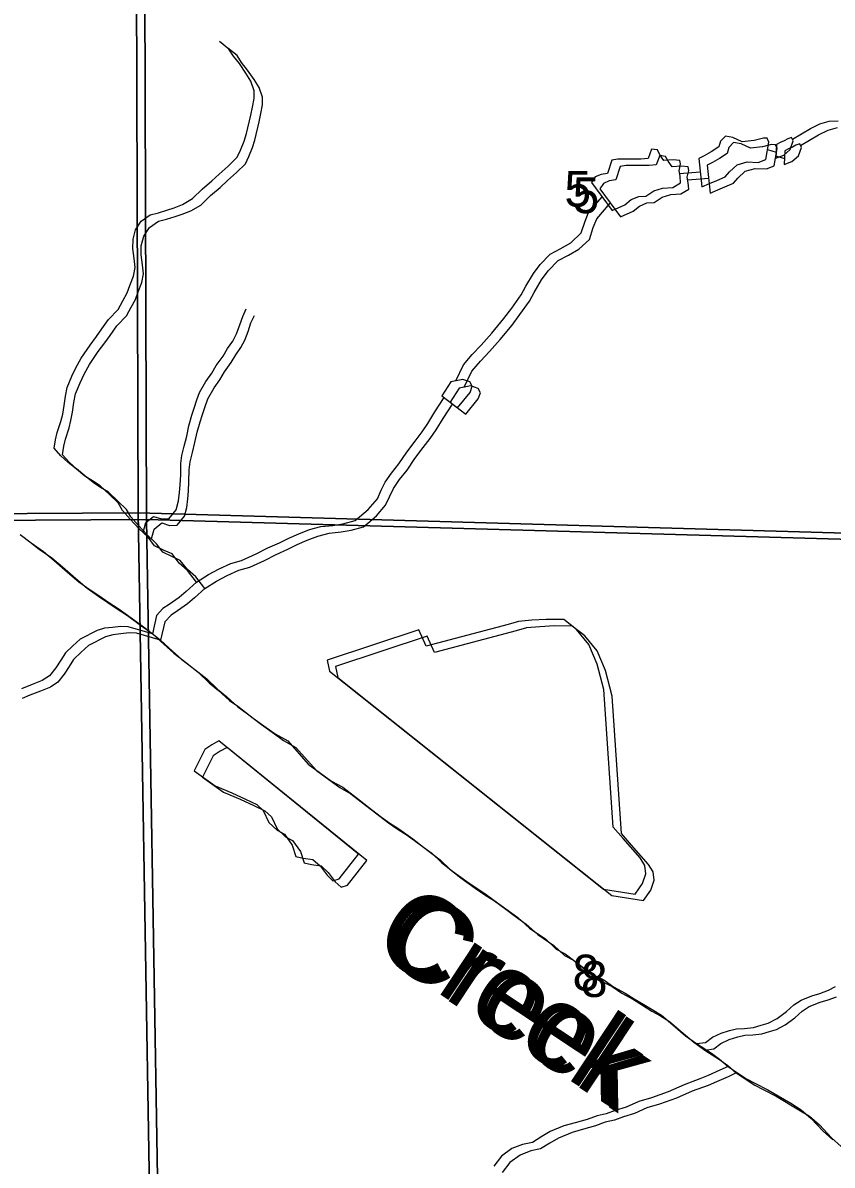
# Model space of a CAD drawing. Extents: x -21.1 to 50.3, y 0 to 22.1.
# Drawn here: x 44.997 to 45.942, y 17.965 to 19.298 of the extents above; entities that cross this region are included whole.
import ezdxf

# ---------------------------------------------------------------- set-up
doc = ezdxf.new("R2010")
doc.units = 0
for name, color, linetype in [('GM_X_Major_River', 7, 'Continuous'), ('GM_X_Major_River_Text', 7, 'Continuous'), ('GM_X_Minor_Lake', 7, 'Continuous'), ('GM_X_Minor_River', 7, 'Continuous'), ('GM_X_Section', 7, 'Continuous'), ('GM_X_Section_Text', 7, 'Continuous')]:
    doc.layers.add(name, color=color, linetype=linetype)

msp = doc.modelspace()

# ---------------------------------------------------------------- linework, layer by layer
at = {"layer": 'GM_X_Major_River'}
for points in [[(44.9936, 18.7011), (45.005, 18.6925), (45.0161, 18.6839), (45.0306, 18.6737), (45.0432, 18.6632), (45.0589, 18.6497), (45.0719, 18.6384), (45.0852, 18.629), (45.0963, 18.6215), (45.1058, 18.6151), (45.1192, 18.6065), (45.1329, 18.5964), (45.1474, 18.5859), (45.1577, 18.5776), (45.1673, 18.5689), (45.1826, 18.555), (45.1979, 18.5434), (45.2116, 18.5325), (45.2242, 18.5204), (45.2349, 18.5114), (45.2479, 18.4998), (45.2575, 18.493), (45.2754, 18.4791), (45.2907, 18.4682), (45.3014, 18.4607), (45.3158, 18.4525), (45.3396, 18.4254), (45.3541, 18.4149), (45.3671, 18.4055), (45.38, 18.3984), (45.3972, 18.3852), (45.4102, 18.3751), (45.4239, 18.3646), (45.4339, 18.3574), (45.4457, 18.3499), (45.4617, 18.3383), (45.4743, 18.3285), (45.4842, 18.3214), (45.4953, 18.3105), (45.5083, 18.3004), (45.5251, 18.2883), (45.5377, 18.2797), (45.5476, 18.2733), (45.561, 18.2636), (45.5705, 18.2564), (45.5846, 18.2463), (45.5984, 18.2339), (45.6171, 18.2212), (45.6293, 18.2095), (45.64, 18.2039), (45.6511, 18.1956), (45.6621, 18.1866), (45.6751, 18.1784), (45.685, 18.1735), (45.6965, 18.1656), (45.7098, 18.1581), (45.7205, 18.1514), (45.7315, 18.1447), (45.7414, 18.139), (45.7521, 18.1323), (45.7655, 18.121), (45.7804, 18.1082), (45.7934, 18.0992), (45.8105, 18.088), (45.8201, 18.0812), (45.83, 18.0726), (45.8414, 18.0647), (45.8518, 18.058), (45.8613, 18.0531), (45.8765, 18.0453), (45.9032, 18.0295), (45.9154, 18.022), (45.9272, 18.0119), (45.941, 17.9968), (45.9525, 17.9867)], [(44.9954, 18.7), (45.0065, 18.6914), (45.021, 18.6812), (45.0336, 18.6707), (45.0492, 18.6572), (45.0622, 18.6459), (45.0756, 18.6365), (45.0867, 18.629), (45.0962, 18.6226), (45.1095, 18.614), (45.1233, 18.6039), (45.1378, 18.5934), (45.1481, 18.5851), (45.1577, 18.5764), (45.173, 18.5625), (45.1882, 18.5509), (45.202, 18.54), (45.2146, 18.5279), (45.2253, 18.5189), (45.2383, 18.5073), (45.2478, 18.5005), (45.2658, 18.4866), (45.281, 18.4757), (45.2917, 18.4682), (45.3062, 18.46), (45.3299, 18.4329), (45.3444, 18.4224), (45.3574, 18.413), (45.3704, 18.4059), (45.3876, 18.3927), (45.4005, 18.3826), (45.4143, 18.3721), (45.4242, 18.3649), (45.436, 18.3574), (45.4521, 18.3458), (45.4647, 18.336), (45.4746, 18.3289), (45.4857, 18.318), (45.4987, 18.3079), (45.5155, 18.2958), (45.528, 18.2872), (45.538, 18.2808), (45.5513, 18.2711), (45.5609, 18.264), (45.575, 18.2538), (45.5887, 18.2414), (45.6074, 18.2287), (45.6197, 18.217), (45.6303, 18.2114), (45.6414, 18.2031), (45.6525, 18.1941), (45.6655, 18.1859), (45.6754, 18.181), (45.6868, 18.1731), (45.7002, 18.1656), (45.7108, 18.1589), (45.7219, 18.1522), (45.7318, 18.1465), (45.7425, 18.1398), (45.7559, 18.1285), (45.7708, 18.1157), (45.7837, 18.1067), (45.8009, 18.0955), (45.8104, 18.0887), (45.8204, 18.0801), (45.8318, 18.0722), (45.8421, 18.0655), (45.8516, 18.0606), (45.8669, 18.0528), (45.8936, 18.037), (45.9058, 18.0295), (45.9176, 18.0194), (45.9314, 18.0043), (45.9429, 17.9942)]]:
    msp.add_lwpolyline(points, dxfattribs=at)
at = {"layer": 'GM_X_Minor_Lake'}
for points in [[(45.7898, 19.107), (45.7989, 19.1109), (45.8072, 19.1144), (45.817, 19.1186), (45.8222, 19.1244), (45.8309, 19.1328), (45.8426, 19.136), (45.8555, 19.1354), (45.8646, 19.1389), (45.8681, 19.159), (45.8662, 19.1636), (45.8616, 19.1639), (45.851, 19.1611), (45.837, 19.1595), (45.826, 19.1647), (45.8172, 19.1661), (45.8116, 19.1603), (45.8098, 19.1535), (45.8007, 19.1477), (45.7925, 19.143), (45.7864, 19.1399)], [(45.8763, 19.1405), (45.8854, 19.144), (45.8929, 19.1506), (45.8965, 19.1605), (45.8946, 19.1646), (45.8901, 19.1631), (45.8859, 19.1607), (45.8814, 19.1588), (45.8769, 19.1565)], [(45.6851, 19.0793), (45.6998, 19.0859), (45.7073, 19.092), (45.716, 19.0956), (45.7243, 19.096), (45.7338, 19.1022), (45.744, 19.1053), (45.7557, 19.1062), (45.7647, 19.1116), (45.7643, 19.1192), (45.7631, 19.1257), (45.7649, 19.1336), (45.7641, 19.1378), (45.7561, 19.1385), (45.7455, 19.1376), (45.7409, 19.1444), (45.7378, 19.15), (45.7309, 19.1511), (45.7269, 19.1401), (45.7185, 19.1392), (45.6916, 19.1393), (45.6848, 19.1381), (45.6797, 19.1225), (45.6721, 19.1213), (45.6653, 19.1185), (45.6608, 19.112)], [(45.7995, 19.0995), (45.8085, 19.1034), (45.8168, 19.1069), (45.8266, 19.1111), (45.8319, 19.1169), (45.8405, 19.1253), (45.8522, 19.1285), (45.8651, 19.1279), (45.8742, 19.1314), (45.8778, 19.1515), (45.8758, 19.1561), (45.8713, 19.1564), (45.8607, 19.1536), (45.8467, 19.152), (45.8356, 19.1572), (45.8269, 19.1586), (45.8212, 19.1528), (45.8194, 19.146), (45.8104, 19.1402), (45.8021, 19.1355), (45.7961, 19.1324)], [(45.8769, 19.1565), (45.8763, 19.1405)], [(45.8859, 19.133), (45.895, 19.1365), (45.9025, 19.1431), (45.9062, 19.153), (45.9042, 19.1571), (45.8997, 19.1556), (45.8956, 19.1532), (45.891, 19.1513), (45.8865, 19.149)], [(45.6947, 19.0718), (45.7094, 19.0784), (45.717, 19.0845), (45.7256, 19.0881), (45.734, 19.0885), (45.7434, 19.0947), (45.7536, 19.0978), (45.7653, 19.0987), (45.7744, 19.1041), (45.7739, 19.1117), (45.7727, 19.1182), (45.7745, 19.1261), (45.7737, 19.1303), (45.7657, 19.131), (45.7551, 19.1301), (45.7505, 19.1369), (45.7474, 19.1425), (45.7406, 19.1436), (45.7365, 19.1326), (45.7282, 19.1317), (45.7013, 19.1318), (45.6944, 19.1306), (45.6893, 19.115), (45.6817, 19.1138), (45.6749, 19.111), (45.6705, 19.1045)], [(45.7864, 19.1399), (45.7898, 19.107)], [(45.8865, 19.149), (45.8859, 19.133)], [(45.7961, 19.1324), (45.7995, 19.0995)], [(45.6608, 19.112), (45.6851, 19.0793)], [(45.6705, 19.1045), (45.6947, 19.0718)], [(45.5045, 18.8489), (45.5191, 18.8669), (45.5217, 18.8741), (45.5189, 18.8791), (45.5106, 18.882), (45.4966, 18.8792), (45.4861, 18.8631)], [(45.5141, 18.8414), (45.5287, 18.8594), (45.5313, 18.8666), (45.5286, 18.8716), (45.5202, 18.8745), (45.5062, 18.8717), (45.4958, 18.8556)], [(45.4861, 18.8631), (45.5045, 18.8489)], [(45.4958, 18.8556), (45.5141, 18.8414)], [(45.3523, 18.5544), (45.3551, 18.5415), (45.675, 18.2869), (45.7119, 18.2812), (45.7204, 18.2935), (45.7245, 18.3049), (45.7232, 18.3147), (45.7178, 18.3234), (45.6979, 18.346), (45.6863, 18.3595), (45.6754, 18.5199), (45.6675, 18.5498), (45.6578, 18.5728), (45.6435, 18.5901), (45.6286, 18.6017), (45.6081, 18.6019), (45.5911, 18.6009), (45.5756, 18.5996), (45.5635, 18.5961), (45.4678, 18.5708), (45.4592, 18.5897)], [(45.3619, 18.5469), (45.3647, 18.534), (45.6846, 18.2794), (45.7215, 18.2737), (45.7301, 18.2859), (45.7341, 18.2974), (45.7329, 18.3072), (45.7275, 18.3159), (45.7075, 18.3385), (45.696, 18.352), (45.6851, 18.5124), (45.6771, 18.5423), (45.6674, 18.5653), (45.6532, 18.5826), (45.6383, 18.5942), (45.6178, 18.5944), (45.6007, 18.5934), (45.5852, 18.5921), (45.5731, 18.5886), (45.4774, 18.5633), (45.4689, 18.5822)], [(45.4592, 18.5897), (45.3523, 18.5544)], [(45.4689, 18.5822), (45.3619, 18.5469)], [(45.2259, 18.46), (45.2177, 18.4554), (45.2094, 18.45), (45.1971, 18.4252), (45.2216, 18.4076), (45.241, 18.3995), (45.257, 18.3921), (45.27, 18.3858), (45.2777, 18.379), (45.2843, 18.365), (45.2939, 18.3557), (45.3023, 18.3512), (45.3115, 18.3384), (45.3158, 18.3252), (45.3242, 18.3233), (45.3356, 18.3216), (45.344, 18.3141), (45.3521, 18.3032), (45.359, 18.2968), (45.3662, 18.2991), (45.389, 18.3278)], [(45.389, 18.3278), (45.2259, 18.46)], [(45.2356, 18.4525), (45.2273, 18.4479), (45.219, 18.4425), (45.2068, 18.4177), (45.2312, 18.4001), (45.2507, 18.392), (45.2667, 18.3846), (45.2796, 18.3783), (45.2873, 18.3715), (45.2939, 18.3575), (45.3035, 18.3482), (45.3119, 18.3437), (45.3211, 18.3309), (45.3255, 18.3177), (45.3338, 18.3158), (45.3452, 18.3141), (45.3536, 18.3066), (45.3617, 18.2957), (45.3686, 18.2893), (45.3758, 18.2916), (45.3986, 18.3203)], [(45.3986, 18.3203), (45.2356, 18.4525)]]:
    msp.add_lwpolyline(points, dxfattribs=at)
at = {"layer": 'GM_X_Minor_River'}
for points in [[(45.1997, 18.6454), (45.1891, 18.659), (45.1795, 18.6677), (45.1711, 18.6783), (45.1619, 18.6824), (45.1508, 18.688), (45.1432, 18.6979), (45.1325, 18.708), (45.1221, 18.719), (45.1133, 18.7292), (45.1083, 18.7379), (45.098, 18.7477), (45.0873, 18.7579), (45.0781, 18.7636), (45.0693, 18.7692), (45.0597, 18.7772), (45.0498, 18.7851), (45.0414, 18.793), (45.0333, 18.8017), (45.0352, 18.8116), (45.037, 18.82), (45.0412, 18.8329), (45.0434, 18.8416), (45.0452, 18.8515), (45.0467, 18.8626), (45.0485, 18.8728), (45.0542, 18.8858), (45.0587, 18.8957), (45.0651, 18.9071), (45.0753, 18.922), (45.0829, 18.9323), (45.0893, 18.941), (45.0968, 18.9521), (45.1082, 18.9639), (45.1138, 18.9739), (45.1187, 18.983), (45.1217, 18.9917), (45.1262, 19.0028), (45.1281, 19.0127), (45.1269, 19.0233), (45.1253, 19.0351), (45.1256, 19.0457), (45.1286, 19.0567), (45.135, 19.067), (45.1456, 19.0743), (45.1551, 19.0766), (45.165, 19.0797), (45.1734, 19.0824), (45.1832, 19.0863), (45.195, 19.0932), (45.2064, 19.1043), (45.2177, 19.1138), (45.2261, 19.1219), (45.2367, 19.131), (45.2473, 19.1414), (45.251, 19.1497), (45.2555, 19.1604), (45.2581, 19.1691), (45.2633, 19.1905), (45.2652, 19.2), (45.267, 19.2102), (45.267, 19.219), (45.2631, 19.2303), (45.2574, 19.2398), (45.2497, 19.2508), (45.2428, 19.2595), (45.2374, 19.2678), (45.2267, 19.2765)], [(45.2093, 18.6379), (45.1987, 18.6515), (45.1891, 18.6602), (45.1807, 18.6708), (45.1716, 18.6749), (45.1605, 18.6805), (45.1528, 18.6903), (45.1421, 18.7005), (45.1318, 18.7115), (45.1229, 18.7217), (45.1179, 18.7304), (45.1076, 18.7402), (45.0969, 18.7504), (45.0877, 18.7561), (45.0789, 18.7617), (45.0694, 18.7697), (45.0594, 18.7776), (45.051, 18.7855), (45.043, 18.7942), (45.0448, 18.8041), (45.0467, 18.8125), (45.0508, 18.8254), (45.053, 18.8341), (45.0549, 18.844), (45.0563, 18.8551), (45.0582, 18.8653), (45.0638, 18.8783), (45.0683, 18.8882), (45.0747, 18.8996), (45.0849, 18.9145), (45.0925, 18.9248), (45.0989, 18.9335), (45.1065, 18.9446), (45.1178, 18.9564), (45.1235, 18.9664), (45.1284, 18.9755), (45.1314, 18.9842), (45.1359, 18.9953), (45.1377, 19.0052), (45.1365, 19.0158), (45.1349, 19.0276), (45.1352, 19.0382), (45.1382, 19.0492), (45.1446, 19.0595), (45.1553, 19.0668), (45.1648, 19.0691), (45.1746, 19.0722), (45.183, 19.0749), (45.1929, 19.0788), (45.2046, 19.0857), (45.216, 19.0968), (45.2274, 19.1063), (45.2357, 19.1144), (45.2463, 19.1235), (45.2569, 19.1339), (45.2607, 19.1422), (45.2652, 19.1529), (45.2678, 19.1616), (45.273, 19.1829), (45.2748, 19.1925), (45.2767, 19.2027), (45.2766, 19.2115), (45.2728, 19.2228), (45.267, 19.2323), (45.2593, 19.2433), (45.2524, 19.252), (45.247, 19.2603), (45.2363, 19.269)], [(45.8955, 19.1627), (45.9165, 19.1751), (45.9274, 19.1805), (45.9384, 19.1837), (45.949, 19.1838)], [(45.9051, 19.1552), (45.9261, 19.1676), (45.9371, 19.173), (45.948, 19.1762)], [(45.8666, 19.1505), (45.8765, 19.1476)], [(45.8763, 19.143), (45.8862, 19.1401)], [(45.7636, 19.1227), (45.788, 19.1245)], [(45.7733, 19.1152), (45.7977, 19.117)], [(45.5024, 18.8804), (45.5115, 18.8991), (45.5216, 18.911), (45.5321, 18.9221), (45.5445, 18.9362), (45.5587, 18.9531), (45.5677, 18.9653), (45.5789, 18.981), (45.5844, 18.9909), (45.593, 19.0058), (45.6008, 19.0162), (45.6125, 19.0284), (45.6245, 19.0346), (45.6366, 19.0416), (45.649, 19.0531), (45.6534, 19.0668), (45.6574, 19.0771), (45.6732, 19.0954)], [(45.5121, 18.8729), (45.5212, 18.8916), (45.5313, 18.9035), (45.5418, 18.9146), (45.5541, 18.9287), (45.5683, 18.9456), (45.5773, 18.9578), (45.5885, 18.9735), (45.5941, 18.9834), (45.6026, 18.9983), (45.6105, 19.0087), (45.6221, 19.0209), (45.6342, 19.0271), (45.6462, 19.0341), (45.6586, 19.0456), (45.663, 19.0593), (45.6671, 19.0696), (45.6828, 19.0879)], [(45.1373, 18.7034), (45.1404, 18.7149), (45.1495, 18.7222), (45.1587, 18.7192), (45.1674, 18.7193), (45.1761, 18.7299), (45.1787, 18.7402), (45.1798, 18.7501), (45.1805, 18.7592), (45.1812, 18.7706), (45.1815, 18.7839), (45.1826, 18.7934), (45.1852, 18.8041), (45.1882, 18.8159), (45.1908, 18.828), (45.1941, 18.8402), (45.1971, 18.8486), (45.2001, 18.8581), (45.2031, 18.8668), (45.2107, 18.8798), (45.2175, 18.8893), (45.2227, 18.8985), (45.2307, 18.9092), (45.236, 18.9183), (45.242, 18.9267), (45.2465, 18.9355), (45.2503, 18.9457), (45.2536, 18.9556), (45.2578, 18.9644)], [(45.147, 18.6959), (45.1501, 18.7074), (45.1591, 18.7147), (45.1683, 18.7117), (45.1771, 18.7118), (45.1857, 18.7224), (45.1884, 18.7327), (45.1894, 18.7426), (45.1902, 18.7517), (45.1908, 18.7631), (45.1912, 18.7764), (45.1922, 18.7859), (45.1948, 18.7966), (45.1978, 18.8084), (45.2004, 18.8205), (45.2038, 18.8327), (45.2068, 18.8411), (45.2098, 18.8506), (45.2128, 18.8593), (45.2203, 18.8723), (45.2271, 18.8818), (45.2324, 18.891), (45.2403, 18.9017), (45.2456, 18.9108), (45.2516, 18.9192), (45.2562, 18.928), (45.2599, 18.9382), (45.2633, 18.9481), (45.2674, 18.9569)], [(45.1997, 18.6454), (45.2135, 18.6542), (45.226, 18.6608), (45.2396, 18.667), (45.2524, 18.6705), (45.2694, 18.6783), (45.283, 18.6853), (45.2965, 18.6915), (45.3075, 18.6969), (45.3192, 18.702), (45.3316, 18.7067), (45.3449, 18.7102), (45.3589, 18.7115), (45.3706, 18.7135), (45.385, 18.7175), (45.4, 18.7302), (45.4109, 18.7428), (45.4153, 18.7527), (45.4201, 18.7623), (45.4272, 18.7726), (45.4358, 18.7837), (45.4452, 18.7971), (45.4549, 18.8101), (45.4631, 18.8208), (45.4698, 18.8307), (45.478, 18.8441), (45.489, 18.8609)], [(45.2093, 18.6379), (45.2232, 18.6467), (45.2356, 18.6533), (45.2492, 18.6595), (45.262, 18.663), (45.279, 18.6708), (45.2926, 18.6778), (45.3062, 18.684), (45.3171, 18.6894), (45.3288, 18.6945), (45.3413, 18.6992), (45.3545, 18.7027), (45.3685, 18.704), (45.3803, 18.706), (45.3946, 18.71), (45.4097, 18.7227), (45.4205, 18.7353), (45.425, 18.7452), (45.4298, 18.7548), (45.4369, 18.7651), (45.4455, 18.7762), (45.4548, 18.7896), (45.4645, 18.8026), (45.4727, 18.8133), (45.4794, 18.8232), (45.4876, 18.8366), (45.4987, 18.8534)], [(45.1997, 18.6454), (45.1876, 18.6345), (45.1793, 18.6276), (45.1677, 18.6195), (45.1605, 18.6145), (45.153, 18.6065), (45.1481, 18.5851)], [(45.2093, 18.6379), (45.1972, 18.627), (45.189, 18.6201), (45.1773, 18.612), (45.1701, 18.607), (45.1626, 18.599), (45.1577, 18.5776)], [(45.1481, 18.5851), (45.1198, 18.5933), (45.1114, 18.5936), (45.1015, 18.5924), (45.0924, 18.5916), (45.0836, 18.5889), (45.0639, 18.5789), (45.0552, 18.5712), (45.0465, 18.5628), (45.0412, 18.5544), (45.0355, 18.5453), (45.028, 18.5361), (45.0196, 18.5304), (45.0079, 18.5258), (44.9953, 18.5208)], [(45.1577, 18.5776), (45.1294, 18.5858), (45.121, 18.5861), (45.1112, 18.5849), (45.102, 18.5841), (45.0933, 18.5814), (45.0735, 18.5714), (45.0648, 18.5637), (45.0561, 18.5553), (45.0508, 18.5469), (45.0452, 18.5378), (45.0376, 18.5286), (45.0293, 18.5229), (45.0175, 18.5183), (45.005, 18.5133), (44.9959, 18.5094)], [(45.7837, 18.1067), (45.794, 18.1081), (45.8023, 18.1142), (45.8122, 18.1188), (45.8221, 18.1219), (45.8304, 18.1239), (45.8396, 18.1243), (45.8502, 18.1255), (45.8589, 18.1282), (45.8673, 18.1305), (45.8776, 18.1359), (45.8885, 18.1443), (45.8973, 18.152), (45.9056, 18.1573), (45.9181, 18.1624), (45.9276, 18.1651), (45.9375, 18.1689), (45.9459, 18.1735)], [(45.7934, 18.0992), (45.8036, 18.1006), (45.8119, 18.1067), (45.8218, 18.1113), (45.8317, 18.1144), (45.8401, 18.1164), (45.8492, 18.1168), (45.8598, 18.118), (45.8686, 18.1207), (45.8769, 18.123), (45.8872, 18.1284), (45.8982, 18.1368), (45.9069, 18.1445), (45.9152, 18.1498), (45.9278, 18.1549), (45.9373, 18.1576), (45.9471, 18.1614)], [(45.8204, 18.0801), (45.8109, 18.0755), (45.7973, 18.0696), (45.7875, 18.0654), (45.769, 18.0587), (45.7505, 18.0505), (45.7308, 18.0435), (45.7161, 18.0392), (45.7014, 18.0326), (45.6885, 18.0286), (45.6779, 18.0247), (45.6674, 18.0223), (45.656, 18.018), (45.642, 18.0141), (45.6288, 18.0105), (45.6126, 18.0039), (45.6028, 17.9981), (45.5919, 17.9912), (45.5805, 17.9888), (45.568, 17.9841), (45.556, 17.9752), (45.547, 17.9637)], [(45.83, 18.0726), (45.8205, 18.068), (45.8069, 18.0621), (45.7971, 18.0579), (45.7786, 18.0512), (45.7601, 18.043), (45.7405, 18.036), (45.7257, 18.0317), (45.711, 18.0251), (45.6982, 18.0211), (45.6876, 18.0172), (45.677, 18.0148), (45.6657, 18.0105), (45.6517, 18.0066), (45.6384, 18.003), (45.6222, 17.9964), (45.6124, 17.9906), (45.6015, 17.9837), (45.5901, 17.9813), (45.5777, 17.9766), (45.5656, 17.9677), (45.5567, 17.9562)]]:
    msp.add_lwpolyline(points, dxfattribs=at)
at = {"layer": 'GM_X_Section'}
for points in [[(44.0863, 19.7149), (45.1286, 19.7159), (45.1314, 18.7262), (44.0935, 18.72)], [(45.1623, 19.7162), (46.1577, 19.7161), (46.1612, 18.6969), (45.1314, 18.7262), (45.1286, 19.7159)], [(44.096, 19.7074), (45.1382, 19.7084), (45.1411, 18.7187), (44.1031, 18.7125)], [(45.1719, 19.7087), (46.1673, 19.7086), (46.1708, 18.6894), (45.1411, 18.7187), (45.1382, 19.7084)], [(44.0935, 18.72), (45.1314, 18.7262), (45.1486, 17.7019), (44.1067, 17.6888), (44.1055, 17.7407), (44.0943, 18.6684)], [(45.1314, 18.7262), (46.1612, 18.6969), (46.1737, 17.6801), (45.7604, 17.6964), (45.1486, 17.7019)], [(44.1031, 18.7125), (45.1411, 18.7187), (45.1583, 17.6944), (44.1163, 17.6813), (44.1151, 17.7332), (44.1039, 18.6609)], [(45.1411, 18.7187), (46.1708, 18.6894), (46.1834, 17.6726), (45.7701, 17.6889), (45.1583, 17.6944)]]:
    msp.add_lwpolyline(points, close=True, dxfattribs=at)

# ---------------------------------------------------------------- texts
at = {"layer": 'GM_X_Major_River_Text'}
for p in [(45.401, 18.2192), (45.4106, 18.2117)]:
    msp.add_text('Creek', height=0.09472, rotation=326.4647, dxfattribs=at).set_placement(p)
at = {"layer": 'GM_X_Section_Text'}
for s, p in [('5', (45.6293, 19.0837)), ('5', (45.6389, 19.0762)), ('8', (45.6388, 18.1686)), ('8', (45.6485, 18.1611))]:
    msp.add_text(s, height=0.0419, rotation=0, dxfattribs=at).set_placement(p)

doc.saveas('drawing.dxf')
